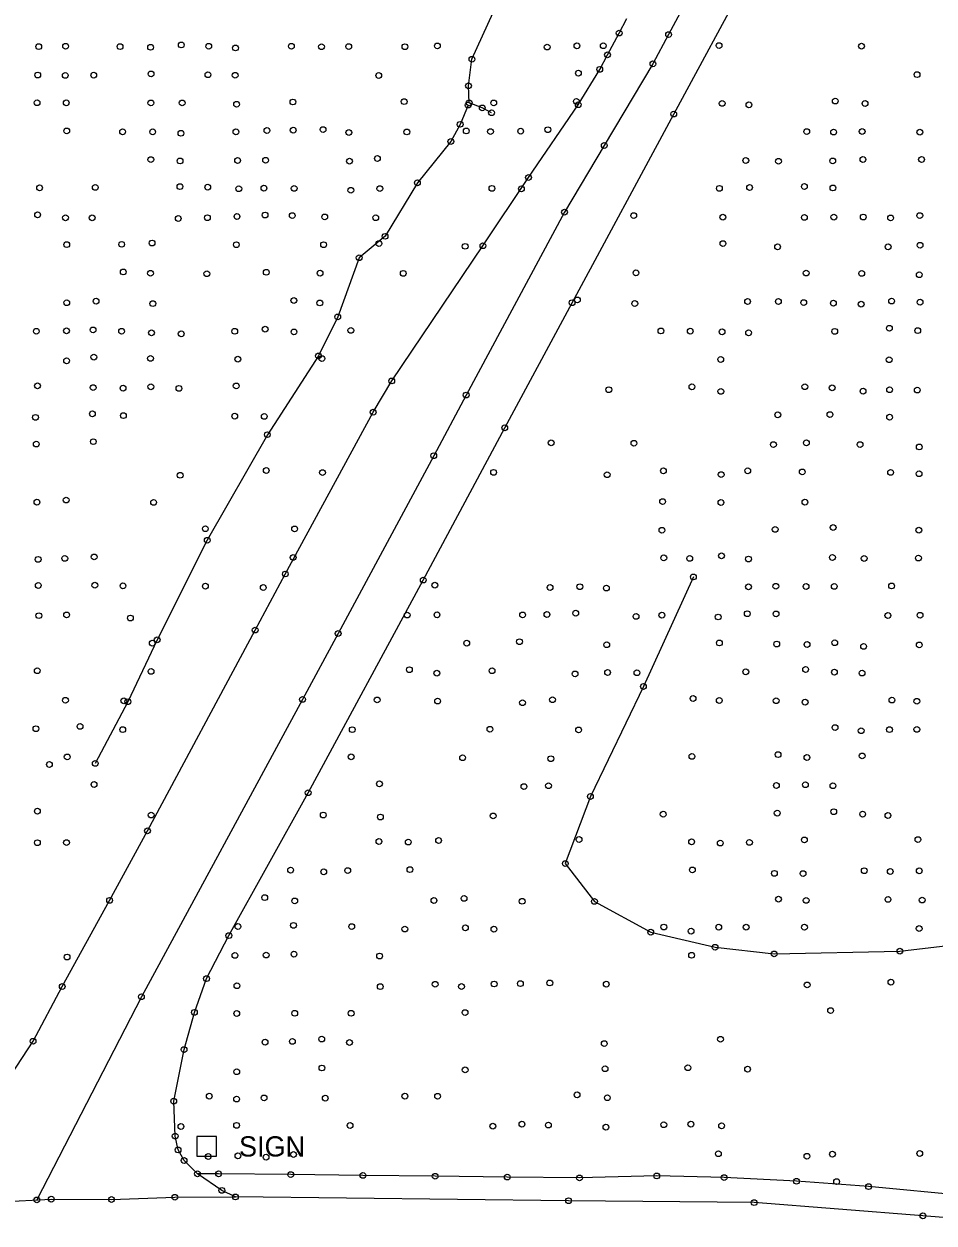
# Model space of a CAD drawing. Extents: x 20503438 to 20508873, y 7964251 to 7984667.
# Drawn here: x 20506082.7 to 20506397.7, y 7970563.1 to 7970978 of the extents above; entities that cross this region are included whole.
import ezdxf

# ---------------------------------------------------------------- set-up
doc = ezdxf.new("R2010")
doc.units = 0
for name, color, linetype in [('SurConcreteSlab', 7, 'Continuous'), ('SurDrainageArrowDown', 7, 'Continuous'), ('SurDrainageArrowUp', 7, 'Continuous'), ('SurEdgeRoadPaved', 7, 'Continuous'), ('SurEdgeShoulderPaved', 7, 'Continuous'), ('SurEdgeShoulderUnpaved', 7, 'Continuous'), ('SurPointsNonDTM', 7, 'Continuous'), ('SurRoadPoints', 7, 'Continuous'), ('SurSurveyPoints', 7, 'Continuous')]:
    doc.layers.add(name, color=color, linetype=linetype)

msp = doc.modelspace()

# ---------------------------------------------------------------- linework, layer by layer
at = {"layer": 'SurConcreteSlab'}
for points in [[(20506513.11, 7971411.74), (20506507.56, 7971394.79), (20506487.08, 7971339.37), (20506464.44, 7971283.88), (20506440, 7971229.86), (20506414.23, 7971176.04), (20506386.11, 7971123.26), (20506358.66, 7971073.06), (20506347.8, 7971052.86), (20506319.35, 7970999.74), (20506305.82, 7970974.38), (20506300.41, 7970964.23), (20506283.57, 7970936), (20506269.79, 7970912.91), (20506235.76, 7970849.63), (20506224.51, 7970828.63), (20506191.46, 7970767.1), (20506179.12, 7970744.28), (20506123.33, 7970641.38), (20506087.13, 7970571.08)], [(20506008.62, 7970569.15), (20506038.99, 7970568.62), (20506092.16, 7970571.34), (20506112.99, 7970571.23), (20506134.91, 7970571.99), (20506155.87, 7970572.09)]]:
    msp.add_lwpolyline(points, dxfattribs=at)
at = {"layer": 'SurDrainageArrowDown'}
for points in [[(20506244.54, 7970947.31), (20506241.33, 7970948.99), (20506236.8, 7970950.75), (20506236.56, 7970956.64), (20506237.77, 7970965.83), (20506248.75, 7970990.23)], [(20506314.39, 7970786.66), (20506297.1, 7970748.77), (20506278.74, 7970710.7), (20506270.08, 7970687.46), (20506280.16, 7970674.38), (20506299.62, 7970663.74), (20506321.92, 7970658.51), (20506342.37, 7970656.22), (20506385.87, 7970657.16), (20506431.83, 7970662.54), (20506454.42, 7970663.63), (20506475.13, 7970663.94), (20506495, 7970659.57), (20506502.32, 7970658.26), (20506511.65, 7970654.17), (20506513.8, 7970653.94), (20506529.03, 7970653.34), (20506552.1, 7970656.67), (20506565.9, 7970659.96), (20506571.22, 7970663.06)]]:
    msp.add_lwpolyline(points, dxfattribs=at)
at = {"layer": 'SurDrainageArrowUp'}
msp.add_lwpolyline([(20506236.43, 7970949.98), (20506233.66, 7970943.31), (20506230.46, 7970937.36), (20506218.86, 7970923.06), (20506207.67, 7970904.55), (20506198.72, 7970897.14), (20506191.29, 7970876.65), (20506184.64, 7970863.17), (20506166.93, 7970835.91), (20506146.15, 7970799.36), (20506128.8, 7970764.92), (20506118.65, 7970743.5), (20506107.37, 7970722.14)], dxfattribs=at)
at = {"layer": 'SurEdgeRoadPaved'}
msp.add_lwpolyline([(20506074.21, 7970608.31), (20506085.84, 7970625.99), (20506095.94, 7970644.94), (20506112.32, 7970674.75), (20506125.46, 7970698.8), (20506162.72, 7970768.29), (20506173.16, 7970787.69), (20506203.58, 7970843.69), (20506210, 7970854.49), (20506241.55, 7970901.3), (20506257.33, 7970924.91), (20506274.55, 7970950.08), (20506281.98, 7970962.34), (20506284.67, 7970967.36), (20506288.7, 7970974.89), (20506291.39, 7970979.91)], dxfattribs=at)
at = {"layer": 'SurEdgeShoulderPaved'}
msp.add_lwpolyline([(20506447.24, 7970561.19), (20506393.85, 7970565.58), (20506335.43, 7970570.13), (20506271.21, 7970570.81), (20506155.87, 7970572.09), (20506151.18, 7970574.39), (20506142.76, 7970580.12), (20506138.12, 7970584.72), (20506136.04, 7970588.36), (20506135.04, 7970593.18), (20506134.52, 7970605.25), (20506138.12, 7970623.09), (20506141.68, 7970635.98), (20506145.89, 7970647.65), (20506153.62, 7970662.54), (20506181.05, 7970711.98), (20506220.89, 7970785.59), (20506249.1, 7970838.29), (20506272.4, 7970881.58), (20506307.59, 7970946.86), (20506333.54, 7970994.99)], dxfattribs=at)
at = {"layer": 'SurEdgeShoulderUnpaved'}
msp.add_lwpolyline([(20506474.18, 7970561.81), (20506449.32, 7970564.35), (20506424.45, 7970566.86), (20506408.85, 7970572.54), (20506375.04, 7970575.67), (20506350.11, 7970577.52), (20506325.07, 7970578.8), (20506301.7, 7970579.36), (20506274.99, 7970578.68), (20506250, 7970578.97), (20506225.01, 7970579.27), (20506200.02, 7970579.56), (20506175.03, 7970579.85), (20506150.05, 7970580.09), (20506142.76, 7970580.12)], dxfattribs=at)
at = {"layer": 'SurPointsNonDTM'}
for centre in [(20506119.53, 7970772.45), (20506102.09, 7970734.94), (20506091.5, 7970721.75)]:
    msp.add_circle(centre, 1, dxfattribs=at)
at = {"layer": 'SurRoadPoints'}
msp.add_lwpolyline([(20506145.92, 7970586.17), (20506145.92, 7970586.17), (20506149.35, 7970586.17), (20506149.35, 7970593.03), (20506142.49, 7970593.03), (20506142.49, 7970586.17), (20506145.92, 7970586.17)], dxfattribs=at)
at = {"layer": 'SurSurveyPoints'}
for centre in [(20506288.7, 7970974.89), (20506305.82, 7970974.38), (20506087.8, 7970970.2), (20506097.12, 7970970.33), (20506115.94, 7970970.2), (20506126.52, 7970969.96), (20506137.15, 7970970.78), (20506146.65, 7970970.33), (20506155.91, 7970969.74), (20506175.25, 7970970.32), (20506185.68, 7970970.16), (20506195.09, 7970970.21), (20506214.55, 7970970.18), (20506225.79, 7970970.45), (20506263.78, 7970970.04), (20506274.1, 7970970.47), (20506283.22, 7970970.5), (20506284.67, 7970967.36), (20506323.3, 7970970.57), (20506372.61, 7970970.35), (20506237.77, 7970965.83), (20506300.41, 7970964.23), (20506087.45, 7970960.38), (20506096.99, 7970960.25), (20506106.84, 7970960.34), (20506126.67, 7970960.75), (20506146.38, 7970960.48), (20506155.8, 7970960.29), (20506205.5, 7970960.21), (20506274.61, 7970961.02), (20506281.98, 7970962.34), (20506391.82, 7970960.51), (20506236.56, 7970956.64), (20506087.23, 7970950.78), (20506097.32, 7970950.75), (20506126.62, 7970950.73), (20506137.45, 7970950.73), (20506175.78, 7970951.04), (20506214.3, 7970951.16), (20506236.8, 7970950.75), (20506245.3, 7970950.72), (20506273.91, 7970951.25), (20506363.51, 7970951.37), (20506156.3, 7970950.26), (20506236.43, 7970949.98), (20506241.33, 7970948.99), (20506244.54, 7970947.31), (20506274.55, 7970950.08), (20506307.59, 7970946.86), (20506324.37, 7970950.54), (20506333.64, 7970950.07), (20506373.82, 7970950.53), (20506233.66, 7970943.31), (20506097.49, 7970941.04), (20506116.84, 7970940.73), (20506127.24, 7970940.7), (20506137.03, 7970940.2), (20506156.07, 7970940.7), (20506166.78, 7970941.16), (20506175.89, 7970941.3), (20506186.23, 7970941.49), (20506195.15, 7970940.48), (20506215.21, 7970940.66), (20506235.81, 7970941.01), (20506244.17, 7970940.8), (20506254.62, 7970940.95), (20506264.02, 7970941.45), (20506353.65, 7970940.8), (20506362.95, 7970940.62), (20506372.83, 7970940.84), (20506392.79, 7970940.59), (20506230.46, 7970937.36), (20506283.57, 7970936), (20506126.59, 7970931.1), (20506136.71, 7970930.63), (20506156.65, 7970930.78), (20506166.34, 7970930.88), (20506195.38, 7970930.55), (20506205.04, 7970931.48), (20506332.54, 7970930.78), (20506343.86, 7970930.54), (20506362.62, 7970930.64), (20506373.1, 7970931.15), (20506393.38, 7970931.15), (20506136.68, 7970921.75), (20506146.3, 7970921.57), (20506218.86, 7970923.06), (20506257.33, 7970924.91), (20506352.83, 7970921.78), (20506088.1, 7970921.32), (20506107.38, 7970921.48), (20506157.05, 7970921.01), (20506165.77, 7970921.22), (20506176.21, 7970921.14), (20506195.82, 7970920.5), (20506205.88, 7970921.07), (20506244.67, 7970921.15), (20506254.88, 7970920.99), (20506323.4, 7970921.15), (20506333.86, 7970921.46), (20506362.7, 7970921.28), (20506087.43, 7970911.98), (20506097.06, 7970910.97), (20506106.3, 7970910.94), (20506136.09, 7970910.72), (20506146.19, 7970911), (20506156.43, 7970911.4), (20506166.15, 7970911.93), (20506175.56, 7970911.73), (20506186.81, 7970911.27), (20506204.46, 7970910.99), (20506269.79, 7970912.91), (20506293.76, 7970911.74), (20506324.59, 7970911.17), (20506352.82, 7970911.09), (20506363.01, 7970911.2), (20506373.21, 7970911.23), (20506382.67, 7970910.93), (20506392.77, 7970911.74), (20506097.5, 7970901.67), (20506116.51, 7970901.78), (20506127.03, 7970902.23), (20506156.2, 7970901.66), (20506186.42, 7970901.66), (20506205.56, 7970902.04), (20506207.67, 7970904.55), (20506235.41, 7970901.09), (20506241.55, 7970901.3), (20506324.64, 7970902.04), (20506343.55, 7970900.91), (20506381.81, 7970900.93), (20506392.87, 7970901.47), (20506198.72, 7970897.14), (20506117.06, 7970892.22), (20506126.48, 7970891.78), (20506146, 7970891.6), (20506166.57, 7970892.1), (20506185.19, 7970891.79), (20506213.98, 7970891.74), (20506294.54, 7970891.9), (20506353.44, 7970891.83), (20506372.66, 7970891.72), (20506392.59, 7970891.26), (20506097.49, 7970881.56), (20506107.65, 7970882.11), (20506127.3, 7970881.25), (20506176.1, 7970882.33), (20506185.1, 7970881.48), (20506272.4, 7970881.58), (20506274.27, 7970882.54), (20506294.12, 7970881.29), (20506333.16, 7970882), (20506343.82, 7970882), (20506352.61, 7970881.62), (20506362.85, 7970881.43), (20506372.48, 7970881.06), (20506383, 7970882.14), (20506392.85, 7970881.75), (20506191.29, 7970876.65), (20506097.42, 7970871.84), (20506106.61, 7970872.17), (20506166.19, 7970872.42), (20506195.82, 7970872), (20506303.16, 7970871.79), (20506382.24, 7970872.73), (20506392.06, 7970871.91), (20506086.97, 7970871.71), (20506116.48, 7970871.69), (20506126.84, 7970871.15), (20506137.12, 7970870.8), (20506155.63, 7970871.68), (20506176.16, 7970871.48), (20506313.31, 7970871.73), (20506324.34, 7970871.51), (20506333.51, 7970871.17), (20506363.32, 7970871.66), (20506097.45, 7970861.48), (20506106.87, 7970862.75), (20506126.5, 7970862.31), (20506156.71, 7970862.05), (20506184.64, 7970863.17), (20506185.83, 7970862.24), (20506323.88, 7970861.94), (20506382.18, 7970861.85), (20506087.38, 7970852.8), (20506106.64, 7970852.2), (20506116.98, 7970852.01), (20506126.61, 7970852.48), (20506136.32, 7970851.94), (20506156.16, 7970852.79), (20506210, 7970854.49), (20506285.12, 7970851.48), (20506313.91, 7970852.48), (20506352.97, 7970852.49), (20506362.44, 7970852.11), (20506382.31, 7970851.45), (20506391.9, 7970851.35), (20506235.76, 7970849.63), (20506323.92, 7970850.88), (20506373.12, 7970850.96), (20506106.38, 7970843.12), (20506203.58, 7970843.69), (20506343.62, 7970842.77), (20506361.68, 7970842.85), (20506086.68, 7970841.9), (20506117.12, 7970842.5), (20506155.66, 7970842.32), (20506165.86, 7970842.24), (20506382.31, 7970841.95), (20506166.93, 7970835.91), (20506249.1, 7970838.29), (20506086.94, 7970832.66), (20506106.7, 7970833.49), (20506265.18, 7970833.08), (20506293.83, 7970832.95), (20506342.12, 7970832.47), (20506353.51, 7970833.07), (20506372.1, 7970832.48), (20506392.58, 7970831.65), (20506224.51, 7970828.63), (20506166.56, 7970823.5), (20506186.04, 7970822.78), (20506245.25, 7970822.87), (20506284.55, 7970822.03), (20506304.04, 7970823.4), (20506324.02, 7970822.1), (20506333.21, 7970823.41), (20506352.08, 7970823.01), (20506382.69, 7970822.84), (20506392.53, 7970822.38), (20506136.76, 7970821.84), (20506087.2, 7970812.56), (20506097.3, 7970813.28), (20506127.56, 7970812.47), (20506303.74, 7970812.76), (20506323.94, 7970812.44), (20506353.01, 7970812.56), (20506145.47, 7970803.35), (20506176.38, 7970803.29), (20506303.51, 7970802.82), (20506342.72, 7970803.13), (20506362.78, 7970803.79), (20506392.44, 7970802.85), (20506146.15, 7970799.36), (20506096.82, 7970793.08), (20506106.99, 7970793.6), (20506175.86, 7970793.39), (20506304.16, 7970793.27), (20506313.13, 7970793.09), (20506324.15, 7970793.97), (20506362.54, 7970793.42), (20506373.51, 7970793.07), (20506392.31, 7970793.21), (20506087.59, 7970792.76), (20506333.48, 7970792.87), (20506173.16, 7970787.69), (20506220.89, 7970785.59), (20506314.39, 7970786.66), (20506087.64, 7970783.73), (20506107.21, 7970783.81), (20506116.97, 7970783.58), (20506145.48, 7970783.47), (20506165.51, 7970783), (20506224.92, 7970783.83), (20506264.79, 7970783.02), (20506275.11, 7970783.3), (20506284.28, 7970782.82), (20506333.48, 7970783.26), (20506342.94, 7970783.45), (20506353.41, 7970783.37), (20506363.16, 7970783.39), (20506383.02, 7970783.54), (20506087.84, 7970773.27), (20506097.46, 7970773.52), (20506215.33, 7970773.48), (20506225.66, 7970773.57), (20506255.29, 7970773.53), (20506263.73, 7970773.68), (20506273.66, 7970774.12), (20506294.55, 7970773.01), (20506303.5, 7970773.43), (20506322.99, 7970772.81), (20506333.07, 7970773.96), (20506343.01, 7970773.88), (20506381.73, 7970773.32), (20506392.85, 7970773.42), (20506162.72, 7970768.29), (20506128.8, 7970764.92), (20506191.46, 7970767.1), (20506254.21, 7970764.27), (20506363.34, 7970763.89), (20506127.1, 7970763.76), (20506235.93, 7970763.76), (20506284.39, 7970763.21), (20506323.39, 7970763.82), (20506343.24, 7970763.46), (20506353.74, 7970763.28), (20506373.32, 7970762.64), (20506392.58, 7970763.15), (20506087.29, 7970754.2), (20506126.68, 7970753.97), (20506216.09, 7970754.57), (20506225.61, 7970753.38), (20506244.71, 7970754.21), (20506273.45, 7970753.12), (20506284.7, 7970753.6), (20506294.88, 7970753.51), (20506332.54, 7970753.83), (20506353.24, 7970754.66), (20506363.23, 7970753.73), (20506372.79, 7970753.4), (20506297.1, 7970748.77), (20506097.05, 7970744), (20506117.27, 7970743.79), (20506118.65, 7970743.5), (20506179.12, 7970744.28), (20506204.96, 7970744.12), (20506225.88, 7970743.71), (20506255.26, 7970743.13), (20506265.63, 7970744.17), (20506314.3, 7970744.6), (20506323.38, 7970743.93), (20506343.06, 7970743.82), (20506353.08, 7970743.35), (20506383.13, 7970744.07), (20506391.76, 7970743.64), (20506086.83, 7970734.15), (20506116.89, 7970733.83), (20506196.34, 7970733.82), (20506243.97, 7970733.95), (20506274.66, 7970733.72), (20506363.43, 7970734.54), (20506372.49, 7970733.45), (20506382.3, 7970733.83), (20506391.74, 7970733.9), (20506097.66, 7970724.38), (20506195.95, 7970724.43), (20506234.51, 7970724.1), (20506265.07, 7970723.78), (20506313.91, 7970724.56), (20506343.72, 7970725.18), (20506353.71, 7970724.2), (20506372.83, 7970724.74), (20506107.37, 7970722.14), (20506106.94, 7970714.85), (20506205.74, 7970715.07), (20506255.77, 7970714.13), (20506264.24, 7970714.42), (20506343.14, 7970714.5), (20506353.18, 7970714.75), (20506362.72, 7970714.42), (20506181.05, 7970711.98), (20506278.74, 7970710.7), (20506087.32, 7970705.6), (20506126.71, 7970704.25), (20506186.3, 7970704.28), (20506206.08, 7970703.58), (20506245.09, 7970703.97), (20506303.96, 7970704.56), (20506343.42, 7970704.94), (20506363, 7970705.43), (20506373, 7970704.59), (20506381.75, 7970704.12), (20506125.46, 7970698.8), (20506087.33, 7970694.7), (20506097.4, 7970694.73), (20506205.56, 7970695.13), (20506215.71, 7970694.92), (20506226.22, 7970695.45), (20506274.83, 7970695.79), (20506313.8, 7970694.99), (20506323.7, 7970694.58), (20506333.81, 7970694.81), (20506352.82, 7970695.66), (20506392.12, 7970695.77), (20506174.99, 7970685.21), (20506194.75, 7970685.06), (20506216.29, 7970685.38), (20506270.08, 7970687.46), (20506314.07, 7970685.27), (20506373.55, 7970685.02), (20506186.45, 7970684.63), (20506342.46, 7970684.09), (20506352.38, 7970684.02), (20506382.56, 7970684.72), (20506392.6, 7970684.96), (20506112.32, 7970674.75), (20506166.02, 7970675.69), (20506176.41, 7970674.56), (20506224.61, 7970674.7), (20506235.04, 7970675.43), (20506255.13, 7970674.42), (20506280.16, 7970674.38), (20506343.88, 7970675.17), (20506353.45, 7970674.73), (20506381.77, 7970675.07), (20506393.59, 7970674.84), (20506156.76, 7970665.68), (20506175.98, 7970666.1), (20506196.14, 7970665.67), (20506214.53, 7970664.81), (20506235.49, 7970665.25), (20506245.38, 7970664.76), (20506304.17, 7970665.52), (20506323.19, 7970665.46), (20506332.67, 7970665.48), (20506352.85, 7970665.45), (20506392.57, 7970664.99), (20506153.62, 7970662.54), (20506299.62, 7970663.74), (20506313.6, 7970664.1), (20506176.16, 7970656.14), (20506321.92, 7970658.51), (20506342.37, 7970656.22), (20506385.87, 7970657.16), (20506097.61, 7970655.14), (20506155.71, 7970655.69), (20506166.52, 7970655.8), (20506205.79, 7970655.48), (20506313.79, 7970655.73), (20506095.94, 7970644.94), (20506145.89, 7970647.65), (20506156.42, 7970645.2), (20506206.02, 7970644.88), (20506225.02, 7970645.7), (20506234.14, 7970644.92), (20506245.43, 7970645.8), (20506254.51, 7970645.92), (20506264.7, 7970646.15), (20506284.24, 7970645.74), (20506353.8, 7970645.47), (20506382.8, 7970646.43), (20506123.33, 7970641.38), (20506141.68, 7970635.98), (20506156.35, 7970635.58), (20506176.4, 7970635.66), (20506195.93, 7970635.65), (20506235.37, 7970635.91), (20506361.89, 7970636.59), (20506085.84, 7970625.99), (20506138.12, 7970623.09), (20506166.13, 7970625.66), (20506175.61, 7970625.94), (20506185.75, 7970626.74), (20506195.36, 7970625.54), (20506283.55, 7970625.17), (20506323.8, 7970626.68), (20506156.32, 7970615.44), (20506185.82, 7970616.73), (20506235.4, 7970616.08), (20506283.83, 7970616.48), (20506312.5, 7970616.82), (20506333.17, 7970616.33), (20506146.83, 7970606.99), (20506165.81, 7970606.38), (20506186.99, 7970606.28), (20506214.54, 7970606.98), (20506225.86, 7970606.94), (20506274.14, 7970607.45), (20506284.62, 7970606.44), (20506134.52, 7970605.25), (20506156.28, 7970605.97), (20506137.01, 7970596.49), (20506156.28, 7970596.88), (20506195.58, 7970596.83), (20506244.99, 7970596.59), (20506255.07, 7970597.29), (20506264.2, 7970596.97), (20506284.13, 7970596.25), (20506304.16, 7970597.1), (20506313.54, 7970597.28), (20506324.17, 7970596.73), (20506135.04, 7970593.18), (20506136.04, 7970588.36), (20506146.48, 7970586.09), (20506156.75, 7970586.33), (20506166.5, 7970585.88), (20506175.98, 7970586.78), (20506323.05, 7970587.05), (20506353.71, 7970586.19), (20506362.54, 7970586.92), (20506392.76, 7970587.15), (20506138.12, 7970584.72), (20506142.76, 7970580.12), (20506142.76, 7970580.12), (20506150.05, 7970580.09), (20506175.03, 7970579.85), (20506200.02, 7970579.56), (20506225.01, 7970579.27), (20506250, 7970578.97), (20506274.99, 7970578.68), (20506301.7, 7970579.36), (20506325.07, 7970578.8), (20506350.11, 7970577.52), (20506363.99, 7970577.4), (20506151.18, 7970574.39), (20506375.04, 7970575.67), (20506087.13, 7970571.08), (20506092.16, 7970571.34), (20506112.99, 7970571.23), (20506134.91, 7970571.99), (20506155.87, 7970572.09), (20506155.87, 7970572.09), (20506271.21, 7970570.81), (20506335.43, 7970570.13), (20506393.85, 7970565.58)]:
    msp.add_circle(centre, 1, dxfattribs=at)

# ---------------------------------------------------------------- texts
at = {"layer": 'SurRoadPoints'}
msp.add_text('SIGN', height=6.995, rotation=360, dxfattribs=at).set_placement((20506157.13, 7970586.1))

doc.saveas('drawing.dxf')
